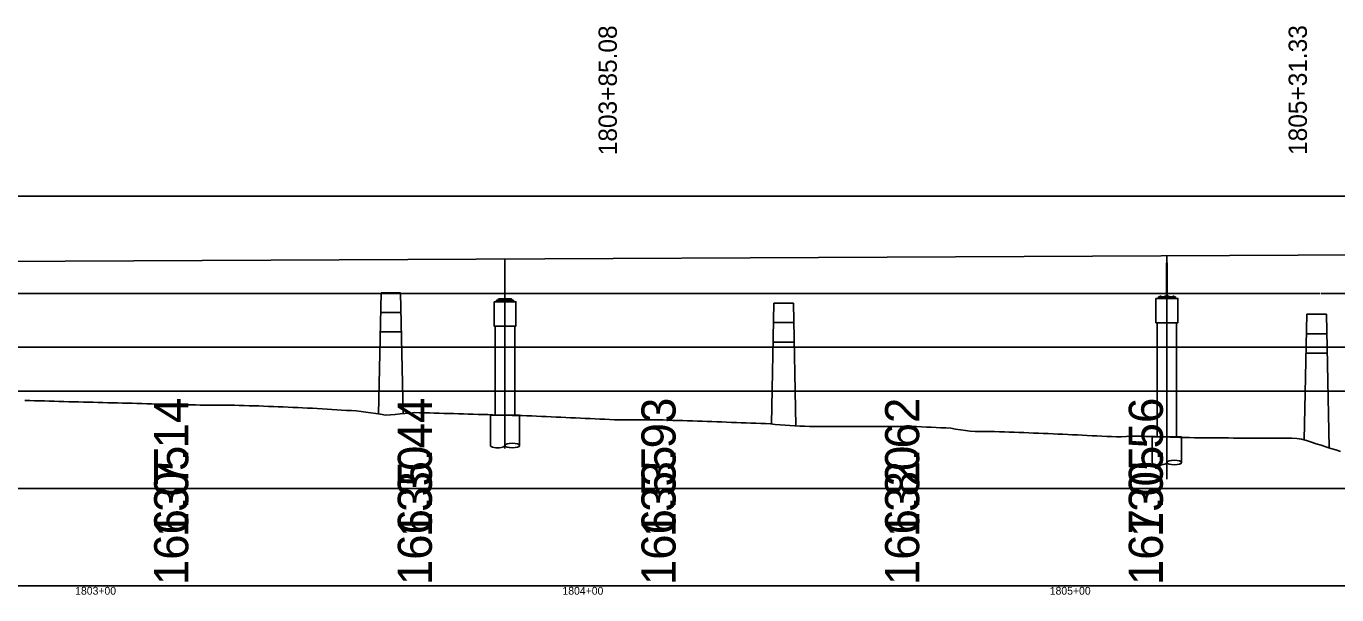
# Model space of a CAD drawing. Extents: x 2126510 to 2136144, y 865066 to 868066.
# Drawn here: x 2128734.5 to 2129003.4, y 866612.1 to 866728.8 of the extents above; entities that cross this region are included whole.
import ezdxf

# ---------------------------------------------------------------- set-up
doc = ezdxf.new("R2010")
doc.units = 0
for name, color, linetype in [('RD_DTM_BkLn1', 7, 'Continuous'), ('RD_EX_Bridge', 7, 'Continuous'), ('RD_EX_GuardRail', 7, 'Continuous'), ('RD_EX_H2O', 7, 'Continuous'), ('RD_EX_Misc', 7, 'Continuous'), ('RD_EX_Misc_Golf_Fairway', 7, 'Continuous'), ('RD_HC_Data', 7, 'Continuous'), ('RD_HC_txCode', 7, 'Continuous')]:
    doc.layers.add(name, color=color, linetype=linetype)

msp = doc.modelspace()

# ---------------------------------------------------------------- linework, layer by layer
at = {"layer": 'RD_DTM_BkLn1'}
for p, q in [((2128834.46, 866672.55), (2128830.96, 866672.55)), ((2128830.96, 866672.55), (2128830.96, 866672.22)), ((2128834.04, 866672.84), (2128831.37, 866672.84)), ((2128831.37, 866672.55), (2128834.04, 866672.55)), ((2128834.46, 866672.22), (2128834.46, 866672.55)), ((2128970.3, 866673.23), (2128966.8, 866673.23)), ((2128966.8, 866673.23), (2128966.8, 866672.9)), ((2128967.21, 866673.23), (2128969.88, 866673.23)), ((2128970.3, 866672.9), (2128970.3, 866673.23)), ((2128830.71, 866667.22), (2128830.71, 866648.91)), ((2128834.71, 866667.22), (2128834.71, 866648.91)), ((2128966.55, 866667.9), (2128966.55, 866644.47)), ((2128970.55, 866667.9), (2128970.55, 866644.47))]:
    msp.add_line(p, q, dxfattribs=at)
for points in [[(2128830.46, 866672.22), (2128834.96, 866672.22), (2128834.96, 866667.22), (2128830.46, 866667.22)], [(2128966.3, 866672.9), (2128970.8, 866672.9), (2128970.8, 866667.9), (2128966.3, 866667.9)]]:
    msp.add_lwpolyline(points, close=True, dxfattribs=at)
for points in [[(2128829.71, 866642.72), (2128829.71, 866648.91), (2128835.71, 866648.91), (2128835.71, 866642.72)], [(2128965.55, 866639.22), (2128965.55, 866644.47), (2128971.55, 866644.47), (2128971.55, 866639.22)]]:
    msp.add_lwpolyline(points, dxfattribs=at)
for centre in [(2128831.21, 866642.72), (2128967.05, 866639.22)]:
    msp.add_ellipse(centre, major_axis=(-1.5, 0), ratio=0.310397, start_param=0, end_param=3.141593, dxfattribs=at)
for centre in [(2128834.21, 866642.72), (2128970.05, 866639.22)]:
    msp.add_ellipse(centre, major_axis=(-1.5, 0), ratio=0.310397, dxfattribs=at)
at = {"layer": 'RD_EX_Bridge'}
for p, q in [((2128831.37, 866672.84), (2128831.37, 866672.55)), ((2128834.04, 866672.55), (2128834.04, 866672.84)), ((2128967.21, 866673.52), (2128967.21, 866673.23)), ((2128968.21, 866673.52), (2128968.21, 866673.23)), ((2128968.88, 866673.23), (2128968.88, 866673.52)), ((2128969.88, 866673.23), (2128969.88, 866673.52))]:
    msp.add_line(p, q, dxfattribs=at)
at = {"layer": 'RD_EX_GuardRail'}
for p, q in [((2131097.7, 866693.9), (2126517.45, 866693.9)), ((2128999.96, 866673.9), (2126517.45, 866673.9)), ((2131097.7, 866673.9), (2129000.13, 866673.9)), ((2131097.7, 866653.9), (2126517.45, 866653.9)), ((2131097.7, 866633.9), (2126517.45, 866633.9)), ((2131097.7, 866613.9), (2126517.45, 866613.9))]:
    msp.add_line(p, q, dxfattribs=at)
at = {"layer": 'RD_EX_H2O'}
for points in [[(2128734.19, 866651.96), (2128735.19, 866651.93), (2128736.19, 866651.9), (2128737.19, 866651.88)], [(2128737.19, 866651.88), (2128738.19, 866651.85), (2128739.19, 866651.82), (2128740.19, 866651.79), (2128741.19, 866651.77), (2128742.19, 866651.74), (2128743.19, 866651.71), (2128744.19, 866651.69), (2128745.19, 866651.66), (2128746.19, 866651.63), (2128747.19, 866651.61), (2128748.19, 866651.58), (2128749.19, 866651.55), (2128750.19, 866651.52), (2128751.19, 866651.5), (2128752.19, 866651.47), (2128753.19, 866651.44), (2128754.19, 866651.42), (2128755.19, 866651.39), (2128756.19, 866651.37), (2128757.19, 866651.34), (2128758.19, 866651.31), (2128759.19, 866651.29), (2128760.19, 866651.26), (2128761.19, 866651.23), (2128762.19, 866651.21), (2128763.19, 866651.18), (2128764.19, 866651.15), (2128765.19, 866651.13), (2128766.19, 866651.1), (2128767.19, 866651.08), (2128768.19, 866651.05), (2128769.19, 866651.03), (2128770.19, 866651), (2128771.19, 866651), (2128772.19, 866650.99), (2128773.19, 866650.98), (2128774.19, 866650.98), (2128775.19, 866650.97), (2128776.19, 866650.96), (2128777.19, 866650.96), (2128778.19, 866650.94), (2128779.19, 866650.91), (2128780.19, 866650.89), (2128781.19, 866650.86), (2128782.19, 866650.83), (2128783.19, 866650.79), (2128784.19, 866650.75), (2128785.19, 866650.71), (2128786.19, 866650.66), (2128787.19, 866650.62), (2128788.19, 866650.58), (2128789.19, 866650.54), (2128790.19, 866650.49), (2128791.19, 866650.45), (2128792.19, 866650.41), (2128793.19, 866650.35), (2128794.19, 866650.29), (2128795.19, 866650.23), (2128796.19, 866650.17), (2128797.19, 866650.11), (2128798.19, 866650.05), (2128799.19, 866649.99), (2128800.19, 866649.93), (2128801.19, 866649.87), (2128802.19, 866649.81), (2128803.19, 866649.7), (2128804.19, 866649.56), (2128805.19, 866649.41), (2128806.19, 866649.26), (2128807.19, 866649.12), (2128808.19, 866648.97), (2128809.19, 866649.01), (2128810.19, 866649.1), (2128811.19, 866649.19), (2128812.19, 866649.29), (2128813.19, 866649.38), (2128814.19, 866649.48), (2128815.19, 866649.45), (2128816.19, 866649.42), (2128817.19, 866649.39), (2128818.19, 866649.36), (2128819.19, 866649.33), (2128820.19, 866649.3), (2128821.19, 866649.28), (2128822.19, 866649.25), (2128823.19, 866649.22), (2128824.19, 866649.19), (2128825.19, 866649.16), (2128826.19, 866649.13), (2128827.19, 866649.11), (2128828.19, 866649.08), (2128829.19, 866649.05), (2128830.19, 866649.02), (2128831.19, 866648.94), (2128832.19, 866648.91), (2128833.19, 866648.91), (2128834.19, 866648.9), (2128835.19, 866648.89), (2128836.19, 866648.87), (2128837.19, 866648.83)], [(2128837.19, 866648.83), (2128838.19, 866648.78), (2128839.19, 866648.74), (2128840.19, 866648.69), (2128841.19, 866648.64), (2128842.19, 866648.6), (2128843.19, 866648.55), (2128844.19, 866648.51), (2128845.19, 866648.46), (2128846.19, 866648.42), (2128847.19, 866648.37), (2128848.19, 866648.32), (2128849.19, 866648.28), (2128850.19, 866648.23), (2128851.19, 866648.19), (2128852.19, 866648.14), (2128853.19, 866648.1), (2128854.19, 866648.05), (2128855.19, 866648.01), (2128856.19, 866648), (2128857.19, 866647.99), (2128858.19, 866647.98), (2128859.19, 866647.97), (2128860.19, 866647.96), (2128861.19, 866647.96), (2128862.19, 866647.95), (2128863.19, 866647.95), (2128864.19, 866647.95), (2128865.19, 866647.95), (2128866.19, 866647.92), (2128867.19, 866647.88), (2128868.19, 866647.85), (2128869.19, 866647.82), (2128870.19, 866647.78), (2128871.19, 866647.75), (2128872.19, 866647.71), (2128873.19, 866647.68), (2128874.19, 866647.64), (2128875.19, 866647.61), (2128876.19, 866647.57), (2128877.19, 866647.54), (2128878.19, 866647.5), (2128879.19, 866647.47), (2128880.19, 866647.43), (2128881.19, 866647.4), (2128882.19, 866647.36), (2128883.19, 866647.33), (2128884.19, 866647.29), (2128885.19, 866647.26), (2128886.19, 866647.23), (2128887.19, 866647.17), (2128888.19, 866647.05), (2128889.19, 866646.94), (2128890.19, 866646.88), (2128891.19, 866646.82), (2128892.19, 866646.77), (2128893.19, 866646.71), (2128894.19, 866646.66), (2128895.19, 866646.63), (2128896.19, 866646.63), (2128897.19, 866646.63), (2128898.19, 866646.63), (2128899.19, 866646.62), (2128900.19, 866646.62), (2128901.19, 866646.62), (2128902.19, 866646.62), (2128903.19, 866646.62), (2128904.19, 866646.62), (2128905.19, 866646.62), (2128906.19, 866646.62), (2128907.19, 866646.62), (2128908.19, 866646.62), (2128909.19, 866646.62), (2128910.19, 866646.62), (2128911.19, 866646.61), (2128912.19, 866646.61), (2128913.19, 866646.61), (2128914.19, 866646.61), (2128915.19, 866646.61), (2128916.19, 866646.61), (2128917.19, 866646.6), (2128918.19, 866646.55), (2128919.19, 866646.5), (2128920.19, 866646.45), (2128921.19, 866646.41), (2128922.19, 866646.36), (2128923.19, 866646.31), (2128924.19, 866646.25), (2128925.19, 866646.1), (2128926.19, 866645.96), (2128927.19, 866645.81), (2128928.19, 866645.66), (2128929.19, 866645.62), (2128930.19, 866645.61), (2128931.19, 866645.59), (2128932.19, 866645.57), (2128933.19, 866645.56), (2128934.19, 866645.54), (2128935.19, 866645.52), (2128936.19, 866645.48), (2128937.19, 866645.44)], [(2128937.19, 866645.44), (2128938.19, 866645.4), (2128939.19, 866645.36), (2128940.19, 866645.32), (2128941.19, 866645.28), (2128942.19, 866645.24), (2128943.19, 866645.2), (2128944.19, 866645.16), (2128945.19, 866645.12), (2128946.19, 866645.07), (2128947.19, 866645.02), (2128948.19, 866644.97), (2128949.19, 866644.93), (2128950.19, 866644.88), (2128951.19, 866644.83), (2128952.19, 866644.78), (2128953.19, 866644.73), (2128954.19, 866644.69), (2128955.19, 866644.64), (2128956.19, 866644.59), (2128957.19, 866644.54), (2128958.19, 866644.49), (2128959.19, 866644.47), (2128960.19, 866644.54), (2128961.19, 866644.6), (2128962.19, 866644.66), (2128963.19, 866644.62), (2128964.19, 866644.59), (2128965.19, 866644.56), (2128966.19, 866644.53), (2128967.19, 866644.51), (2128968.19, 866644.48), (2128969.19, 866644.45), (2128970.19, 866644.42), (2128971.19, 866644.39), (2128972.19, 866644.37), (2128973.19, 866644.34), (2128974.19, 866644.31), (2128975.19, 866644.29), (2128976.19, 866644.28), (2128977.19, 866644.28), (2128978.19, 866644.27), (2128979.19, 866644.27), (2128980.19, 866644.26), (2128981.19, 866644.26), (2128982.19, 866644.25), (2128983.19, 866644.25), (2128984.19, 866644.24), (2128985.19, 866644.24), (2128986.19, 866644.23), (2128987.19, 866644.23), (2128988.19, 866644.22), (2128989.19, 866644.22), (2128990.19, 866644.21), (2128991.19, 866644.21), (2128992.19, 866644.2), (2128993.19, 866644.2), (2128994.19, 866644.19), (2128995.19, 866644.18), (2128996.19, 866644.04), (2128997.19, 866643.73), (2128998.19, 866643.41), (2128999.19, 866643.09), (2129000.19, 866642.76), (2129001.19, 866642.44), (2129002.19, 866642.12), (2129003.19, 866641.8), (2129004.19, 866641.48)]]:
    msp.add_lwpolyline(points, dxfattribs=at)
at = {"layer": 'RD_EX_Misc'}
for p, q in [((2127961.73, 866676.62), (2129142.37, 866682.52)), ((2127368.72, 866613.9), (2131522.97, 866613.9))]:
    msp.add_line(p, q, dxfattribs=at)
msp.add_lwpolyline([(2127275.85, 866613.9), (2127275.85, 866662.9), (2131989.68, 866662.9)], dxfattribs=at)
at = {"layer": 'RD_EX_Misc_Golf_Fairway'}
for p, q in [((2128807.28, 866674.03), (2128806.77, 866649.18)), ((2128811.28, 866674.03), (2128807.28, 866674.03)), ((2128811.28, 866674.03), (2128811.8, 866649.25)), ((2128887.91, 866671.95), (2128887.39, 866647.14)), ((2128891.91, 866671.95), (2128887.91, 866671.95)), ((2128891.91, 866671.95), (2128892.43, 866646.76)), ((2128811.37, 866670.03), (2128807.21, 866670.03)), ((2128997.28, 866669.65), (2128996.75, 866643.87)), ((2129001.28, 866669.65), (2128997.28, 866669.65)), ((2129001.28, 866669.65), (2129001.85, 866642.23)), ((2128891.99, 866667.95), (2128887.84, 866667.95)), ((2128811.45, 866666.03), (2128807.12, 866666.03)), ((2128892.07, 866663.95), (2128887.74, 866663.95)), ((2129001.37, 866665.65), (2128997.21, 866665.65)), ((2129001.45, 866661.65), (2128997.12, 866661.65))]:
    msp.add_line(p, q, dxfattribs=at)
at = {"layer": 'RD_HC_Data'}
for p, q in [((2128832.71, 866680.97), (2128832.71, 866642.13)), ((2128968.55, 866681.65), (2128968.55, 866635.79))]:
    msp.add_line(p, q, dxfattribs=at)
at = {"layer": 'RD_HC_txCode'}
for p, q in [((2128968.46, 866680.23), (2128968.46, 866673.52)), ((2128968.63, 866680.23), (2128968.63, 866673.52))]:
    msp.add_line(p, q, dxfattribs=at)

# ---------------------------------------------------------------- texts
at = {"layer": 'RD_EX_Misc'}
for s, height, p in [('1803+85.08', 3.75, (2128855.67, 866702.29)), ('1805+31.33', 3.75, (2128997.28, 866702.35)), ('137.14', 7, (2128767.72, 866623.9)), ('135.44', 7, (2128817.72, 866623.9)), ('133.93', 7, (2128867.72, 866623.9)), ('132.62', 7, (2128917.72, 866623.9)), ('130.56', 7, (2128967.72, 866623.9)), ('166.05', 7, (2128767.72, 866614.05)), ('166.30', 7, (2128817.72, 866614.05)), ('166.55', 7, (2128867.72, 866614.05)), ('166.80', 7, (2128917.72, 866614.05)), ('167.05', 7, (2128967.72, 866614.05))]:
    msp.add_text(s, height=height, rotation=90, dxfattribs=at).set_placement(p)
for s, p in [('1803+00', (2128744.51, 866612.1)), ('1804+00', (2128844.51, 866612.1)), ('1805+00', (2128944.51, 866612.1))]:
    msp.add_text(s, height=1.6, dxfattribs=at).set_placement(p)

doc.saveas('drawing.dxf')
